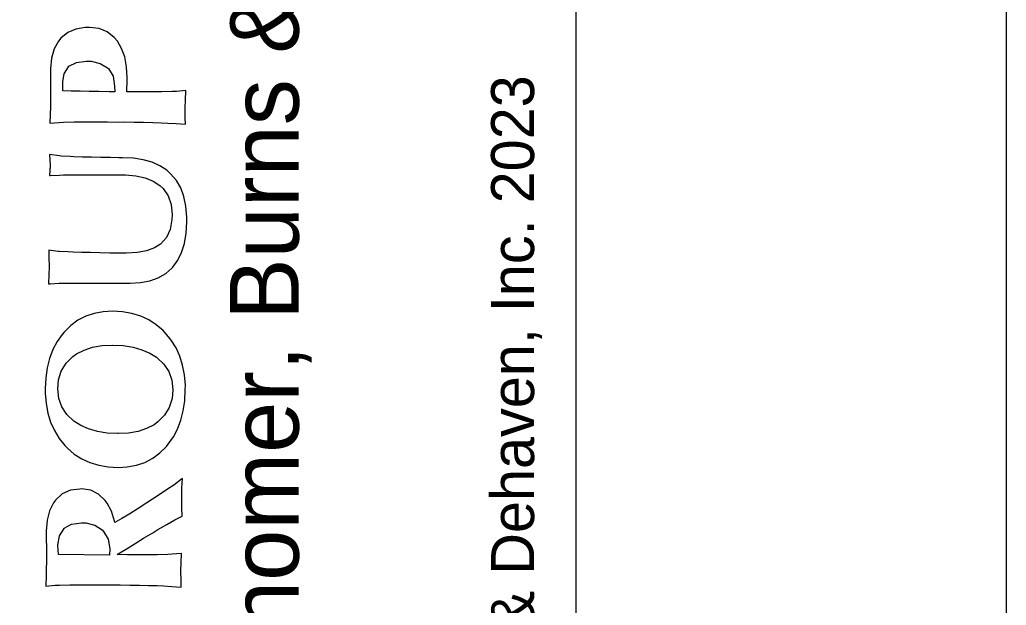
# Model space of a CAD drawing. Extents: x 0 to 34, y 0 to 22.
# Drawn here: x 32.854 to 34, y 20.006 to 20.686 of the extents above; entities that cross this region are included whole.
import ezdxf

# ---------------------------------------------------------------- set-up
doc = ezdxf.new("R2010")
doc.units = 0
for name, color, linetype in [('SH_Border', 7, 'Continuous'), ('SH_Cut_Line', 7, 'Continuous'), ('SH_Data', 7, 'Continuous')]:
    doc.layers.add(name, color=color, linetype=linetype)

msp = doc.modelspace()

# ---------------------------------------------------------------- linework, layer by layer
at = {"layer": 'SH_Border'}
msp.add_lwpolyline([(2, 21.5), (33.5, 21.5), (33.5, 0.5), (2, 0.5)], close=True, dxfattribs=at)
at = {"layer": 'SH_Cut_Line'}
msp.add_lwpolyline([(0, 22), (34, 22), (34, 0), (0, 0)], close=True, dxfattribs=at)
at = {"layer": 'SH_Data'}
for points in [[(32.9636, 20.6652), (32.9555, 20.6717), (32.946, 20.6756), (32.9349, 20.6769), (32.9299, 20.6768), (32.9189, 20.6749), (32.9095, 20.6708), (32.9016, 20.6645), (32.8987, 20.6609), (32.8936, 20.6519), (32.8906, 20.6412), (32.8895, 20.6288), (32.8896, 20.5852), (32.8889, 20.5657), (32.8997, 20.5665), (32.9048, 20.5668), (32.917, 20.5671), (32.9234, 20.5672), (32.9336, 20.5672), (32.9445, 20.5673), (32.9559, 20.5671), (32.9677, 20.567), (32.9754, 20.5671), (32.9868, 20.5669), (32.9977, 20.5668), (33.0083, 20.5665), (33.0182, 20.5661), (33.026, 20.5658), (33.0355, 20.5653), (33.0464, 20.5643), (33.0461, 20.5718), (33.0461, 20.5839), (33.0462, 20.5924), (33.0467, 20.6034), (33.0359, 20.6026), (33.0308, 20.6024), (33.0186, 20.6021), (33.0116, 20.602), (33.0011, 20.602), (32.99, 20.6019), (32.9783, 20.602), (32.9787, 20.6163), (32.9787, 20.6183), (32.978, 20.631), (32.9758, 20.6425), (32.9722, 20.6523), (32.9674, 20.6609), (32.9636, 20.6652)], [(32.9674, 20.6609), (32.9636, 20.6652), (32.9555, 20.6717), (32.946, 20.6756), (32.9349, 20.6769), (32.9299, 20.6768), (32.9189, 20.6749), (32.9095, 20.6708), (32.9016, 20.6645)], [(32.9674, 20.6609), (32.9636, 20.6652), (32.9555, 20.6717), (32.946, 20.6756), (32.9349, 20.6769), (32.9299, 20.6768), (32.9189, 20.6749), (32.9095, 20.6708), (32.9016, 20.6645)], [(32.9016, 20.6645), (32.8987, 20.6609), (32.8936, 20.6519), (32.8906, 20.6412)], [(32.978, 20.631), (32.9758, 20.6425), (32.9722, 20.6523), (32.9674, 20.6609)], [(32.8906, 20.6412), (32.8895, 20.6288)], [(32.9039, 20.614), (32.9053, 20.623), (32.911, 20.6317), (32.9196, 20.6363), (32.9311, 20.6378), (32.9367, 20.6375), (32.9474, 20.6351), (32.9556, 20.6301), (32.9569, 20.6291), (32.9623, 20.6202), (32.964, 20.6086), (32.9641, 20.6021)], [(32.9641, 20.6021), (32.9576, 20.6022), (32.9458, 20.6023), (32.9345, 20.6026), (32.9239, 20.6028), (32.9136, 20.603), (32.9039, 20.6033), (32.9039, 20.614), (32.9053, 20.623), (32.911, 20.6317), (32.9196, 20.6363), (32.9311, 20.6378), (32.9367, 20.6375), (32.9474, 20.6351), (32.9556, 20.6301), (32.9569, 20.6291), (32.9623, 20.6202), (32.964, 20.6086), (32.9641, 20.6021)], [(32.9039, 20.614), (32.9053, 20.623), (32.911, 20.6317), (32.9196, 20.6363), (32.9311, 20.6378), (32.9367, 20.6375), (32.9474, 20.6351), (32.9556, 20.6301), (32.9569, 20.6291), (32.9623, 20.6202), (32.964, 20.6086), (32.9641, 20.6021)], [(32.8895, 20.6288), (32.8896, 20.5852)], [(32.9783, 20.602), (32.9787, 20.6163), (32.9787, 20.6183), (32.978, 20.631)], [(32.9783, 20.602), (32.9787, 20.6163), (32.9787, 20.6183), (32.978, 20.631)], [(32.9641, 20.6021), (32.9576, 20.6022), (32.9458, 20.6023), (32.9345, 20.6026), (32.9239, 20.6028), (32.9136, 20.603), (32.9039, 20.6033), (32.9039, 20.614)], [(33.0461, 20.5839), (33.0462, 20.5924), (33.0467, 20.6034), (33.0467, 20.6034), (33.0359, 20.6026), (33.0308, 20.6024), (33.0186, 20.6021), (33.0116, 20.602), (33.0011, 20.602), (32.99, 20.6019), (32.9783, 20.602)], [(32.8896, 20.5852), (32.8889, 20.5657)], [(33.0355, 20.5653), (33.0464, 20.5643), (33.0461, 20.5718), (33.0461, 20.5839)], [(32.8889, 20.5657), (32.8997, 20.5665), (32.9048, 20.5668), (32.917, 20.5671), (32.9234, 20.5672), (32.9336, 20.5672), (32.9445, 20.5673), (32.9559, 20.5671), (32.9677, 20.567), (32.9754, 20.5671), (32.9868, 20.5669), (32.9977, 20.5668), (33.0083, 20.5665), (33.0182, 20.5661), (33.026, 20.5658), (33.0355, 20.5653), (33.0355, 20.5653)], [(32.947, 20.4151), (32.936, 20.4153), (32.9256, 20.4156), (32.9156, 20.4158), (32.9096, 20.4162), (32.8996, 20.4167), (32.8985, 20.4168), (32.8875, 20.4181), (32.8877, 20.4106), (32.8879, 20.3985), (32.8877, 20.3899), (32.8872, 20.379), (32.889, 20.3791), (32.8997, 20.3799), (32.9035, 20.38), (32.9153, 20.38), (32.9676, 20.3798), (32.9819, 20.3797), (32.9941, 20.3806), (33.0051, 20.3826), (33.0148, 20.3862), (33.0234, 20.391), (33.0305, 20.3973), (33.0318, 20.3986), (33.0375, 20.4065), (33.0419, 20.4155), (33.0452, 20.426), (33.0472, 20.438), (33.0479, 20.4511), (33.048, 20.4566), (33.0468, 20.4692), (33.0444, 20.4803), (33.0408, 20.4904), (33.0358, 20.4991), (33.0295, 20.5066), (33.0248, 20.5109), (33.0167, 20.5161), (33.0077, 20.5202), (32.9973, 20.523), (32.9858, 20.5249), (32.9731, 20.5254), (32.9688, 20.5255), (32.9594, 20.5257), (32.948, 20.5258), (32.937, 20.526), (32.9266, 20.5263), (32.9167, 20.5267), (32.9123, 20.5268), (32.9021, 20.5275), (32.8996, 20.5278), (32.8885, 20.5292), (32.8885, 20.5287), (32.889, 20.5165), (32.8883, 20.5048), (32.9, 20.5054), (32.9045, 20.5056), (32.9165, 20.5057), (32.9687, 20.5055), (32.9741, 20.5055), (32.9765, 20.5055), (32.9888, 20.5043), (32.9996, 20.5021), (33.0089, 20.4984), (33.0165, 20.4934), (33.0204, 20.4899), (33.0264, 20.4813), (33.0298, 20.4712), (33.0309, 20.4592), (33.0306, 20.4539), (33.0285, 20.4422), (33.0241, 20.4327), (33.0175, 20.4253), (33.0104, 20.4207), (33.0011, 20.4173), (32.9901, 20.4153), (32.9773, 20.4147), (32.9677, 20.4147), (32.9584, 20.4148), (32.947, 20.4151)], [(33.0305, 20.3973), (33.0318, 20.3986), (33.0375, 20.4065), (33.0419, 20.4155), (33.0452, 20.426), (33.0472, 20.438), (33.0479, 20.4511), (33.048, 20.4566), (33.0468, 20.4692), (33.0444, 20.4803), (33.0408, 20.4904), (33.0358, 20.4991), (33.0295, 20.5066), (33.0248, 20.5109), (33.0167, 20.5161), (33.0077, 20.5202), (32.9973, 20.523), (32.9858, 20.5249), (32.9731, 20.5254), (32.9688, 20.5255), (32.9594, 20.5257), (32.948, 20.5258), (32.937, 20.526), (32.9266, 20.5263), (32.9167, 20.5267), (32.9123, 20.5268), (32.9021, 20.5275), (32.8996, 20.5278), (32.8885, 20.5292)], [(32.8885, 20.5292), (32.8885, 20.5287), (32.889, 20.517)], [(32.889, 20.517), (32.889, 20.5161), (32.8883, 20.5047)], [(32.8883, 20.5047), (32.8892, 20.5048)], [(32.8892, 20.5048), (32.9, 20.5054), (32.9045, 20.5056), (32.9165, 20.5057), (32.9687, 20.5055), (32.9741, 20.5055), (32.9765, 20.5055), (32.9888, 20.5043), (32.9996, 20.5021), (33.0089, 20.4984), (33.0165, 20.4934), (33.0204, 20.4899), (33.0264, 20.4813), (33.0298, 20.4712), (33.0309, 20.4592)], [(33.0309, 20.4592), (33.0306, 20.4539), (33.0285, 20.4422), (33.0241, 20.4327), (33.0175, 20.4253), (33.0104, 20.4207), (33.0011, 20.4173), (32.9901, 20.4153), (32.9773, 20.4147), (32.9677, 20.4147), (32.9584, 20.4148), (32.947, 20.4151), (32.936, 20.4153), (32.9256, 20.4156), (32.9156, 20.4158), (32.9096, 20.4162), (32.8996, 20.4167), (32.8985, 20.4168), (32.8875, 20.4181)], [(32.8875, 20.4181), (32.8877, 20.4106), (32.8879, 20.3985)], [(32.8879, 20.3985), (32.8877, 20.3899), (32.8872, 20.379)], [(32.889, 20.3791), (32.8997, 20.3799), (32.9035, 20.38), (32.9153, 20.38), (32.9676, 20.3798), (32.98, 20.3797), (32.9819, 20.3797), (32.9941, 20.3806), (33.0051, 20.3826), (33.0148, 20.3862), (33.0234, 20.391), (33.0305, 20.3973)], [(32.8872, 20.379), (32.889, 20.3791)], [(32.9616, 20.3473), (32.9509, 20.3466), (32.9404, 20.3447), (32.9304, 20.3415), (32.9213, 20.3367), (32.913, 20.3305), (32.9053, 20.3229), (32.9032, 20.3204), (32.8972, 20.3119), (32.8924, 20.3027), (32.8885, 20.2925), (32.8858, 20.2815), (32.8841, 20.2699), (32.8834, 20.2573), (32.8835, 20.252), (32.8844, 20.24), (32.8865, 20.2287), (32.8897, 20.2183), (32.8941, 20.2086), (32.8995, 20.1996), (32.9062, 20.1913), (32.9094, 20.1881), (32.9172, 20.1814), (32.926, 20.1759), (32.9353, 20.1717), (32.9456, 20.1686), (32.9564, 20.1666), (32.968, 20.1659), (32.9786, 20.1664), (32.9893, 20.1683), (32.9993, 20.1717), (33.0083, 20.1765), (33.0167, 20.1826), (33.0243, 20.1902), (33.0263, 20.1928), (33.0323, 20.2012), (33.0372, 20.2104), (33.041, 20.2206), (33.0437, 20.2316), (33.0456, 20.2433), (33.0461, 20.2558), (33.0462, 20.2613), (33.0451, 20.2733), (33.043, 20.2846), (33.0398, 20.295), (33.0354, 20.3047), (33.0299, 20.3137), (33.0233, 20.3219), (33.0203, 20.3249), (33.0124, 20.3316), (33.0037, 20.3372), (32.9943, 20.3415), (32.9841, 20.3446), (32.9733, 20.3464), (32.9616, 20.3473)], [(33.0323, 20.2012), (33.0372, 20.2104), (33.041, 20.2206), (33.0437, 20.2316), (33.0456, 20.2433), (33.0461, 20.2558), (33.0462, 20.2613), (33.0451, 20.2733), (33.043, 20.2846), (33.0398, 20.295), (33.0354, 20.3047), (33.0299, 20.3137), (33.0233, 20.3219), (33.0203, 20.3249), (33.0124, 20.3316), (33.0037, 20.3372), (32.9943, 20.3415), (32.9841, 20.3446), (32.9733, 20.3464), (32.9616, 20.3473), (32.9509, 20.3466), (32.9404, 20.3447), (32.9304, 20.3415), (32.9213, 20.3367), (32.913, 20.3305), (32.9053, 20.3229), (32.9032, 20.3204), (32.8972, 20.3119)], [(33.0323, 20.2012), (33.0372, 20.2104), (33.041, 20.2206), (33.0437, 20.2316), (33.0456, 20.2433), (33.0461, 20.2558), (33.0462, 20.2613), (33.0451, 20.2733), (33.043, 20.2846), (33.0398, 20.295), (33.0354, 20.3047), (33.0299, 20.3137), (33.0233, 20.3219), (33.0203, 20.3249), (33.0124, 20.3316), (33.0037, 20.3372), (32.9943, 20.3415), (32.9841, 20.3446), (32.9733, 20.3464), (32.9616, 20.3473), (32.9509, 20.3466), (32.9404, 20.3447), (32.9304, 20.3415), (32.9213, 20.3367), (32.913, 20.3305), (32.9053, 20.3229), (32.9032, 20.3204), (32.8972, 20.3119)], [(32.8972, 20.3119), (32.8924, 20.3027), (32.8885, 20.2925), (32.8858, 20.2815), (32.8841, 20.2699), (32.8834, 20.2573)], [(32.9553, 20.2058), (32.944, 20.2077), (32.9338, 20.2105), (32.9248, 20.2145), (32.9166, 20.2196), (32.9084, 20.2272), (32.9026, 20.2361), (32.8991, 20.2459), (32.898, 20.2572), (32.899, 20.2674), (32.9021, 20.2778), (32.9077, 20.2868), (32.9154, 20.2946), (32.9197, 20.2977), (32.9285, 20.3022), (32.9383, 20.3056), (32.9494, 20.3074), (32.9617, 20.308), (32.9741, 20.3073), (32.9855, 20.3055), (32.9956, 20.3026), (33.0048, 20.2986), (33.0128, 20.2937), (33.013, 20.2935), (33.0213, 20.2859), (33.0271, 20.2771), (33.0305, 20.2671), (33.0317, 20.256), (33.0307, 20.2457), (33.0274, 20.2355), (33.022, 20.2265), (33.0143, 20.2187), (33.0099, 20.2154), (33.0012, 20.2109), (32.9914, 20.2075), (32.9802, 20.2056), (32.9678, 20.2051), (32.9553, 20.2058)], [(32.898, 20.2572), (32.899, 20.2674), (32.9021, 20.2778), (32.9077, 20.2868), (32.9154, 20.2946), (32.9197, 20.2977), (32.9285, 20.3022), (32.9383, 20.3056), (32.9494, 20.3074), (32.9616, 20.308), (32.9618, 20.308), (32.9741, 20.3073), (32.9855, 20.3055), (32.9956, 20.3026), (33.0048, 20.2986), (33.0128, 20.2937), (33.013, 20.2935), (33.0213, 20.2859), (33.0271, 20.2771), (33.0305, 20.2671), (33.0317, 20.256)], [(32.898, 20.2572), (32.899, 20.2674), (32.9021, 20.2778), (32.9077, 20.2868), (32.9154, 20.2946), (32.9197, 20.2977), (32.9285, 20.3022), (32.9383, 20.3056), (32.9494, 20.3074), (32.9616, 20.308), (32.9618, 20.308), (32.9741, 20.3073), (32.9855, 20.3055), (32.9956, 20.3026), (33.0048, 20.2986), (33.0128, 20.2937), (33.013, 20.2935), (33.0213, 20.2859), (33.0271, 20.2771), (33.0305, 20.2671), (33.0317, 20.256)], [(32.8834, 20.2573), (32.8835, 20.252), (32.8844, 20.24), (32.8865, 20.2287), (32.8897, 20.2183), (32.8941, 20.2086), (32.8995, 20.1996), (32.9062, 20.1913), (32.9094, 20.1881), (32.9172, 20.1814), (32.926, 20.1759), (32.9353, 20.1717), (32.9456, 20.1686), (32.9564, 20.1666), (32.968, 20.1659), (32.9786, 20.1664), (32.9893, 20.1683), (32.9993, 20.1717), (33.0083, 20.1765), (33.0167, 20.1826), (33.0243, 20.1902), (33.0263, 20.1928), (33.0323, 20.2012)], [(33.0317, 20.256), (33.0307, 20.2457), (33.0274, 20.2355), (33.022, 20.2265), (33.0143, 20.2187), (33.0099, 20.2154), (33.0012, 20.2109), (32.9914, 20.2075), (32.9802, 20.2056), (32.9681, 20.2052), (32.9675, 20.2052), (32.9553, 20.2058), (32.944, 20.2077), (32.9338, 20.2105), (32.9248, 20.2145), (32.9166, 20.2196), (32.9166, 20.2196), (32.9084, 20.2272), (32.9026, 20.2361), (32.8991, 20.2459), (32.898, 20.2572)], [(32.9789, 20.0643), (32.9671, 20.0646), (32.9702, 20.0666), (32.9787, 20.0718), (32.9879, 20.0775), (32.9977, 20.0836), (33.0083, 20.09), (33.0144, 20.0936), (33.0247, 20.0995), (33.034, 20.1048), (33.0424, 20.1092), (33.0421, 20.1189), (33.0421, 20.1311), (33.0423, 20.1423), (33.0428, 20.1531), (33.0417, 20.1522), (33.0327, 20.1454), (33.0254, 20.1404), (33.0145, 20.1331), (33.0014, 20.1246), (32.9913, 20.1182), (32.9815, 20.1121), (32.9724, 20.1065), (32.9641, 20.1017), (32.9637, 20.1036), (32.9604, 20.1149), (32.9554, 20.1243), (32.9531, 20.1276), (32.9454, 20.1349), (32.9362, 20.1393), (32.9255, 20.1409), (32.9236, 20.1407), (32.9127, 20.1393), (32.9032, 20.135), (32.8955, 20.128), (32.8929, 20.1246), (32.8883, 20.1154), (32.8855, 20.1046), (32.8845, 20.0919), (32.8848, 20.0634), (32.8846, 20.0409), (32.8839, 20.0281), (32.8948, 20.029), (32.8998, 20.0291), (32.9121, 20.0296), (32.9184, 20.0295), (32.9287, 20.0296), (32.9395, 20.0296), (32.9509, 20.0296), (32.9627, 20.0295), (32.9704, 20.0295), (32.9818, 20.0292), (32.9928, 20.0291), (33.0033, 20.0289), (33.0133, 20.0286), (33.021, 20.0283), (33.0306, 20.0277), (33.0414, 20.0266), (33.0412, 20.0341), (33.0411, 20.0463), (33.0412, 20.0549), (33.0418, 20.0659), (33.0309, 20.065), (33.0259, 20.0647), (33.0136, 20.0644), (33.011, 20.0644), (33.0009, 20.0643), (32.9902, 20.0642), (32.9789, 20.0643)], [(33.0417, 20.1522), (33.0327, 20.1454), (33.0254, 20.1404), (33.0145, 20.1331), (33.0014, 20.1246), (32.9913, 20.1182), (32.9815, 20.1121), (32.9724, 20.1065), (32.9641, 20.1017)], [(33.0421, 20.1311), (33.0423, 20.1423), (33.0428, 20.1531), (33.0417, 20.1522)], [(33.0421, 20.1311), (33.0423, 20.1423), (33.0428, 20.1531), (33.0417, 20.1522)], [(32.9604, 20.1149), (32.9554, 20.1243), (32.9531, 20.1276), (32.9454, 20.1349), (32.9362, 20.1393), (32.9255, 20.1409), (32.9236, 20.1407), (32.9127, 20.1393), (32.9032, 20.135), (32.8955, 20.128), (32.8929, 20.1246), (32.8883, 20.1154), (32.8855, 20.1046)], [(32.9671, 20.0646), (32.9702, 20.0666), (32.9787, 20.0718), (32.9879, 20.0775), (32.9977, 20.0836), (33.0083, 20.09), (33.0144, 20.0936), (33.0247, 20.0995), (33.034, 20.1048), (33.0424, 20.1092), (33.0421, 20.1189), (33.0421, 20.1311)], [(32.9641, 20.1017), (32.9637, 20.1036), (32.9604, 20.1149)], [(32.8855, 20.1046), (32.8845, 20.0919)], [(32.9582, 20.0641), (32.8988, 20.0646), (32.8981, 20.0755), (32.8998, 20.0863), (32.9053, 20.0949), (32.9055, 20.0952), (32.914, 20.1), (32.9254, 20.1016), (32.9306, 20.1013), (32.9412, 20.0986), (32.9496, 20.0932), (32.9512, 20.0916), (32.9567, 20.0826), (32.9585, 20.0713), (32.9582, 20.0641)], [(32.8981, 20.0755), (32.8998, 20.0863), (32.9053, 20.0949), (32.9055, 20.0952), (32.914, 20.1), (32.9254, 20.1016), (32.9306, 20.1013), (32.9412, 20.0986), (32.9496, 20.0932), (32.9512, 20.0916), (32.9567, 20.0826), (32.9585, 20.0713)], [(32.8845, 20.0919), (32.8848, 20.0634), (32.8846, 20.0409)], [(32.9585, 20.0713), (32.9582, 20.0641), (32.8988, 20.0646), (32.8981, 20.0755)], [(33.0411, 20.0463), (33.0412, 20.0549), (33.0418, 20.0659), (33.0418, 20.0659), (33.0309, 20.065), (33.0259, 20.0647), (33.0136, 20.0644), (33.011, 20.0644), (33.0009, 20.0643), (32.9902, 20.0642), (32.9789, 20.0643), (32.9671, 20.0646)], [(32.8846, 20.0409), (32.8839, 20.0281)], [(33.0306, 20.0277), (33.0414, 20.0266), (33.0412, 20.0341), (33.0411, 20.0463)], [(32.8839, 20.0281), (32.8948, 20.029)], [(32.8948, 20.029), (32.8998, 20.0291), (32.9121, 20.0296), (32.9184, 20.0295), (32.9287, 20.0296), (32.9395, 20.0296), (32.9509, 20.0296), (32.9627, 20.0295), (32.9704, 20.0295), (32.9818, 20.0292), (32.9928, 20.0291), (33.0033, 20.0289), (33.0133, 20.0286), (33.021, 20.0283), (33.0306, 20.0277), (33.0306, 20.0277)]]:
    msp.add_lwpolyline(points, dxfattribs=at)

# ---------------------------------------------------------------- texts
for s, height, p in [('Glaus, Pyle, Schomer, Burns & DeHaven, Inc.', 0.08, (33.1779, 19.2433)), ('Copyright: Glaus, Pyle, Schomer, Burns & Dehaven, Inc. 2023', 0.05, (33.4514, 18.7779))]:
    msp.add_text(s, height=height, rotation=90, dxfattribs=at).set_placement(p)

doc.saveas('drawing.dxf')
